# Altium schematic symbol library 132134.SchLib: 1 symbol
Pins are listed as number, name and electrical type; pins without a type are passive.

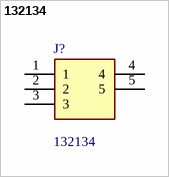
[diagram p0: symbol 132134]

## 132134
designator J?
RF Connectors / Coaxial Connectors SMA STRAIGHT PCB RECEPTACLE; Manufacturer_Name: Amphenol; Geometry.Height: 9.53mm
footprint 132134
pins: 1, 2, 3, 4, 5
